// Mitsubishi GX Works2 project: SK2N RS通讯例程   PLC: FX2N/FX2NC

PROGRAM MAIN
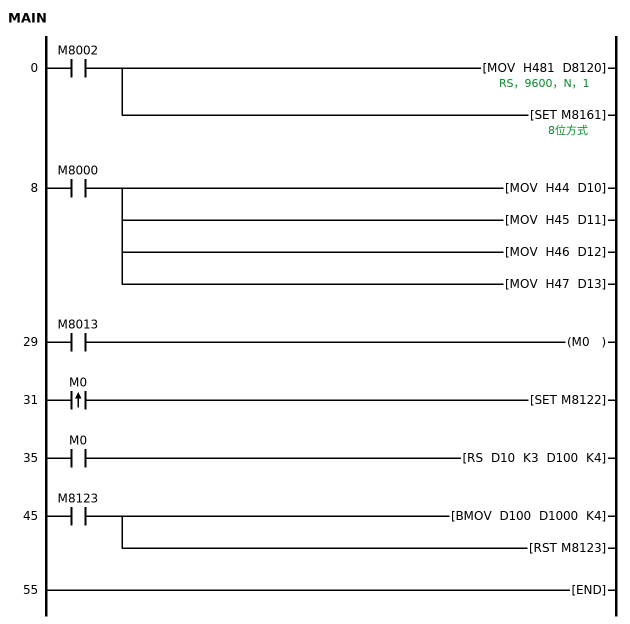
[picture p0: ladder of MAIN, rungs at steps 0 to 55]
0     LD      M8002
      MOV     H481 D8120  ; RS，9600，N，1
      SET     M8161  ; 8位方式
8     LD      M8000
      MOV     H44 D10
      MOV     H45 D11
      MOV     H46 D12
      MOV     H47 D13
29    LD      M8013
      OUT     M0
31    LDP     M0
      SET     M8122
35    LD      M0
      RS      D10 K3 D100 K4
45    LD      M8123
      BMOV    D100 D1000 K4
      RST     M8123
55    END
END_PROGRAM
